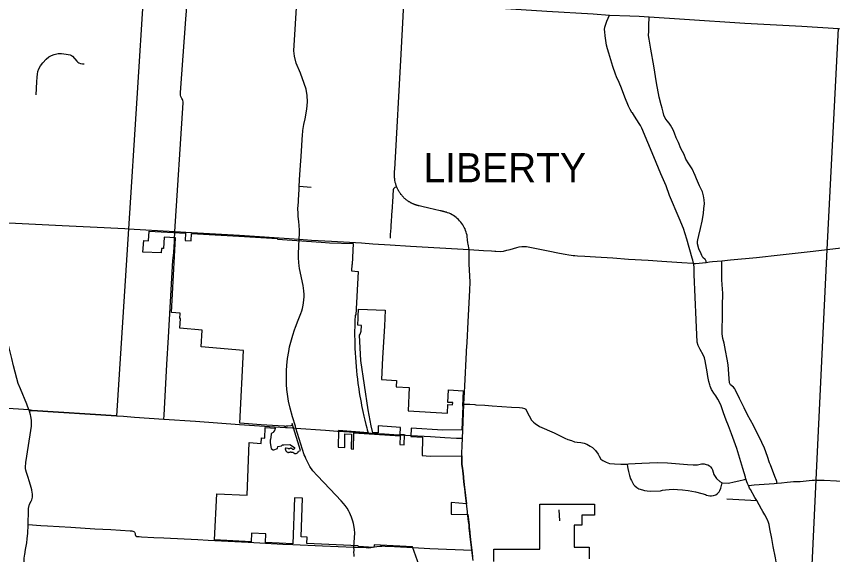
# Model space of a CAD drawing. Extents: x 1729596 to 1925846, y 659247 to 911751.
# Drawn here: x 1793175 to 1818365, y 790627 to 807237 of the extents above; entities that cross this region are included whole.
import ezdxf

# ---------------------------------------------------------------- set-up
doc = ezdxf.new("R2010")
doc.units = 0
for name, color, linetype in [('GM_X_City_Street', 7, 'Continuous'), ('GM_X_Corporation', 7, 'Continuous'), ('GM_X_County_Road', 7, 'Continuous'), ('GM_X_State_Route', 7, 'Continuous'), ('GM_X_Township', 7, 'Continuous'), ('GM_X_Township_Road', 7, 'Continuous'), ('GM_X_Township_Text', 7, 'Continuous')]:
    doc.layers.add(name, color=color, linetype=linetype)

msp = doc.modelspace()

# ---------------------------------------------------------------- linework, layer by layer
at = {"layer": 'GM_X_City_Street'}
for points in [[(1798056, 800391), (1798063, 800548)], [(1803593, 790860), (1803616, 791303), (1803610, 791407), (1803592, 791535), (1803581, 791586), (1803562, 791662), (1803522, 791785), (1803491, 791860), (1803460, 791928), (1803435, 791974), (1803382, 792063), (1803323, 792149), (1803275, 792210), (1803202, 792291), (1802860, 792647), (1802459, 793065), (1802327, 793219), (1802237, 793347), (1802189, 793427), (1802146, 793510), (1802106, 793595), (1802083, 793653), (1802061, 793711), (1801804, 794534), (1801785, 794592), (1801697, 794877), (1801622, 795149), (1801577, 795364), (1801553, 795508), (1801526, 795726), (1801515, 795873), (1801507, 796108), (1801512, 796313), (1801521, 796460), (1801544, 796679), (1801579, 796897), (1801608, 797041), (1801643, 797184), (1801704, 797397), (1801763, 797566), (1801790, 797645), (1801875, 797866), (1801954, 798071), (1801981, 798146), (1802004, 798222), (1802028, 798325), (1802041, 798401), (1802054, 798578), (1802056, 798612), (1802055, 798689), (1802052, 798741), (1802049, 798768), (1802040, 798846), (1802024, 798932), (1801916, 799454), (1801901, 799536), (1801889, 799641), (1801880, 799782), (1801880, 799852), (1801882, 799923), (1801901, 800359)], [(1801699, 794541), (1801804, 794534), (1802711, 794469), (1803088, 794442)], [(1805195, 794317), (1805349, 794307)], [(1809918, 792015), (1809918, 792014), (1809933, 791671)], [(1803969, 790844), (1804052, 790841), (1804223, 790866), (1804297, 790877), (1804388, 790887), (1804454, 790894), (1804503, 790896), (1804556, 790893)], [(1805411, 790847), (1805932, 790816), (1807231, 790763)]]:
    msp.add_lwpolyline(points, dxfattribs=at)
at = {"layer": 'GM_X_Corporation'}
for points in [[(1805912, 789433), (1805403, 790869), (1804215, 790928), (1804211, 790853), (1803721, 790877), (1803722, 790895), (1802140, 790967), (1802146, 791168), (1801964, 791178), (1802002, 792366), (1801754, 792380), (1801709, 790966), (1800866, 791005), (1800878, 791273), (1800432, 791295), (1800421, 791026), (1799291, 791085), (1799361, 792508), (1800301, 792459), (1800358, 794084), (1800732, 794059), (1800745, 794232), (1800840, 794226), (1800850, 794556), (1801177, 794531), (1801177, 794530), (1801171, 794528), (1801167, 794526), (1801164, 794523), (1801161, 794520), (1801159, 794516), (1801158, 794513), (1801157, 794509), (1801156, 794499), (1801152, 794484), (1801149, 794473), (1801144, 794460), (1801136, 794444), (1801131, 794435), (1801124, 794425), (1801117, 794416), (1801111, 794410), (1801105, 794403), (1801097, 794396), (1801057, 794378), (1801046, 794370), (1801040, 794358), (1801038, 794353), (1801037, 794349), (1801036, 794346), (1801035, 794342), (1801034, 794334), (1801015, 794183), (1801013, 794166), (1801010, 794148), (1801006, 794125), (1801005, 794119), (1801004, 794113), (1801004, 794107), (1801004, 794104), (1801004, 794102), (1801004, 794098), (1801004, 794092), (1801005, 794088), (1801006, 794083), (1801044, 793903), (1801076, 793875), (1801081, 793871), (1801084, 793869), (1801087, 793868), (1801092, 793865), (1801097, 793864), (1801100, 793863), (1801105, 793863), (1801111, 793862), (1801118, 793863), (1801122, 793864), (1801126, 793865), (1801230, 793905), (1801243, 793966), (1801357, 793982), (1801392, 794015), (1801434, 794020), (1801618, 794023), (1801754, 793933), (1801757, 793926), (1801759, 793919), (1801759, 793910), (1801757, 793900), (1801752, 793890), (1801748, 793886), (1801742, 793880), (1801732, 793875), (1801726, 793874), (1801720, 793873), (1801711, 793874), (1801703, 793877), (1801698, 793880), (1801693, 793884), (1801686, 793893), (1801676, 793902), (1801667, 793907), (1801657, 793909), (1801646, 793910), (1801638, 793909), (1801629, 793906), (1801619, 793902), (1801607, 793898), (1801595, 793897), (1801583, 793896), (1801571, 793897), (1801564, 793899), (1801556, 793901), (1801506, 793918), (1801497, 793919), (1801489, 793918), (1801482, 793914), (1801477, 793908), (1801474, 793903), (1801474, 793901), (1801473, 793897), (1801473, 793892), (1801475, 793878), (1801477, 793871), (1801479, 793864), (1801482, 793854), (1801487, 793844), (1801496, 793829), (1801505, 793818), (1801515, 793807), (1801525, 793798), (1801538, 793790), (1801540, 793788), (1801545, 793786), (1801549, 793784), (1801554, 793783), (1801561, 793782), (1801566, 793782), (1801570, 793782), (1801575, 793783), (1801582, 793785), (1801594, 793789), (1801606, 793792), (1801618, 793794), (1801629, 793795), (1801640, 793796), (1801650, 793796), (1801660, 793795), (1801677, 793793), (1801690, 793790), (1801706, 793785), (1801719, 793780), (1801741, 793765), (1801773, 793752), (1801811, 793754), (1801832, 793757), (1801855, 793773), (1801876, 793794), (1801883, 793816), (1801890, 793824), (1801945, 793843), (1801685, 794670), (1801687, 794665), (1801687, 794660), (1801688, 794655), (1801688, 794651), (1801687, 794646), (1801686, 794641), (1801682, 794632), (1801676, 794623), (1801669, 794616), (1801665, 794613), (1801657, 794609), (1801650, 794606), (1801644, 794605), (1801555, 794593), (1801526, 794589), (1801506, 794588), (1801484, 794587), (1801464, 794587), (1801447, 794588), (1801432, 794588), (1800727, 794638), (1800069, 794684), (1800187, 796930), (1798881, 797044), (1798908, 797551), (1798221, 797611), (1798237, 797910), (1798217, 797912), (1798226, 798077), (1797968, 798095), (1798088, 800399), (1797739, 800419), (1797716, 800075), (1797653, 800079), (1797641, 799936), (1797084, 799963), (1797107, 800322), (1797255, 800313), (1797272, 800613), (1798397, 800551), (1798384, 800322), (1798575, 800308), (1798585, 800540), (1800039, 800457), (1801236, 800382), (1801235, 800362), (1802581, 800268), (1802843, 800252), (1803573, 800232), (1803539, 799580), (1803531, 799580), (1803521, 799381), (1803720, 799367), (1803650, 798018), (1803630, 798018), (1803626, 797950), (1803625, 797907), (1803622, 797844), (1803621, 797776), (1803619, 797715), (1803615, 797472), (1803615, 797362), (1803616, 797275), (1803619, 797126), (1803624, 796988), (1803629, 796858), (1803638, 796706), (1803659, 796433), (1803671, 796297), (1803684, 796179), (1803700, 796040), (1803716, 795913), (1803741, 795740), (1803759, 795626), (1803776, 795519), (1803792, 795428), (1803803, 795369), (1803812, 795318), (1803830, 795229), (1803848, 795137), (1803866, 795049), (1803900, 794897), (1803929, 794774), (1803961, 794644), (1803989, 794539), (1804002, 794484), (1804028, 794390), (1803117, 794454), (1803108, 793948), (1803307, 793934), (1803315, 794360), (1803513, 794346), (1803505, 793891), (1803582, 793885), (1803590, 794385), (1805020, 794290), (1805010, 794022), (1805139, 794014), (1805152, 794324), (1805017, 794332), (1805027, 794547), (1804342, 794598), (1804342, 794383), (1804179, 794385), (1804129, 794602), (1804037, 795099), (1803808, 796623), (1803760, 797403), (1803781, 797434), (1803819, 797522), (1803830, 797703), (1803712, 797708), (1803713, 797757), (1803719, 797888), (1803723, 797985), (1803733, 798207), (1804556, 798175), (1804535, 797675), (1804476, 796703), (1804448, 796035), (1804906, 795999), (1804898, 795810), (1805300, 795785), (1805269, 795066), (1806477, 794993), (1806488, 795256), (1806639, 795253), (1806642, 795323), (1806493, 795326), (1806509, 795712), (1806963, 795684), (1806943, 795206), (1806953, 795205), (1806921, 794476), (1806338, 794471), (1805355, 794530), (1805348, 794275), (1805706, 794254), (1805701, 793689), (1805942, 793669), (1806920, 793676), (1806923, 793473), (1806927, 793423), (1806942, 793287), (1806949, 793228), (1806961, 793116), (1806970, 793038), (1806976, 792990), (1806999, 792792), (1807038, 792455), (1807068, 792201), (1806589, 792240), (1806589, 791873), (1807104, 791869), (1807144, 791544), (1807151, 791476), (1807153, 791456), (1807155, 791437), (1807184, 791193), (1807215, 790917), (1807231, 790763), (1807256, 790572)], [(1807905, 790417), (1807905, 790798), (1809332, 790798), (1809332, 792187), (1811020, 792187), (1811020, 791842), (1810623, 791842), (1810623, 791542), (1810391, 791542), (1810391, 790858), (1810855, 790858), (1810855, 790494)]]:
    msp.add_lwpolyline(points, dxfattribs=at)
at = {"layer": 'GM_X_County_Road'}
for points in [[(1797153, 808138), (1797813, 808094), (1798478, 808064), (1798746, 808039), (1801838, 807850), (1803855, 807737), (1803954, 807731), (1804251, 807713), (1804397, 807702), (1804736, 807682), (1805136, 807661), (1806811, 807563), (1808119, 807486), (1809547, 807399), (1810973, 807310), (1811477, 807276), (1812106, 807251), (1812390, 807244), (1812704, 807223), (1813792, 807154), (1815652, 807028), (1817412, 806933), (1818544, 806864), (1818913, 806840)], [(1798065, 800600), (1798320, 804569), (1798319, 804604), (1798313, 804638), (1798300, 804669), (1798280, 804702), (1798255, 804766), (1798245, 804805), (1798244, 804890), (1798409, 807145), (1798478, 808064)], [(1802014, 803669), (1802020, 803715), (1802050, 803896), (1802085, 804077), (1802143, 804374), (1802164, 804595), (1802153, 804796), (1802119, 804993), (1802057, 805167), (1801945, 805481), (1801815, 805789), (1801757, 806010), (1801735, 806174), (1801838, 807850)], [(1804844, 802293), (1804843, 802302), (1804842, 802313), (1804841, 802319), (1804844, 802370), (1804849, 802458), (1804852, 802514), (1805055, 806072), (1805110, 807232), (1805136, 807661)], [(1801953, 802776), (1801962, 802915), (1802006, 803596), (1802014, 803669)], [(1801927, 802355), (1801953, 802776)], [(1801904, 801987), (1801904, 801993), (1801927, 802355)], [(1806860, 800922), (1806855, 800928), (1806820, 800964), (1806783, 800999), (1806745, 801031), (1806705, 801061), (1806663, 801090), (1806620, 801115), (1806575, 801139), (1806529, 801160), (1806483, 801179), (1806464, 801186), (1806456, 801189), (1806449, 801191), (1806443, 801192), (1806431, 801196), (1806423, 801198), (1806414, 801200), (1806401, 801204), (1806388, 801207), (1806381, 801209), (1806371, 801212), (1806359, 801215), (1806347, 801218), (1806336, 801220), (1806324, 801223), (1806314, 801226), (1806302, 801229), (1806289, 801233), (1806283, 801235), (1806276, 801237), (1806266, 801239), (1806257, 801241), (1805899, 801322), (1805693, 801369), (1805607, 801388), (1805581, 801394), (1805570, 801397), (1805562, 801399), (1805554, 801401), (1805547, 801403), (1805539, 801405), (1805530, 801408), (1805521, 801412), (1805511, 801415), (1805503, 801418), (1805495, 801421), (1805486, 801424), (1805470, 801430), (1805454, 801436), (1805439, 801442), (1805424, 801449), (1805408, 801455), (1805393, 801462), (1805386, 801466), (1805378, 801470), (1805363, 801477), (1805349, 801485), (1805334, 801493), (1805319, 801501), (1805305, 801510), (1805291, 801518), (1805277, 801527), (1805263, 801537), (1805249, 801546), (1805236, 801556), (1805223, 801566), (1805209, 801576), (1805196, 801586), (1805184, 801597), (1805171, 801608), (1805158, 801619), (1805146, 801630), (1805134, 801642), (1805122, 801654), (1805111, 801666), (1805099, 801678), (1805088, 801690), (1805077, 801703), (1805066, 801715), (1805056, 801728), (1805045, 801741), (1805035, 801755), (1805025, 801768), (1805016, 801782), (1805006, 801795), (1804997, 801809), (1804988, 801823), (1804980, 801838), (1804971, 801852), (1804963, 801867), (1804955, 801881), (1804948, 801896), (1804940, 801911), (1804933, 801926), (1804926, 801941), (1804920, 801957), (1804914, 801972), (1804911, 801979), (1804907, 801988), (1804896, 802019), (1804882, 802065), (1804869, 802115), (1804855, 802189), (1804854, 802197), (1804852, 802214), (1804850, 802230), (1804849, 802247), (1804848, 802263), (1804847, 802274), (1804844, 802293), (1804844, 802293)], [(1801882, 801567), (1801899, 801907), (1801904, 801987)], [(1801907, 800780), (1801897, 800907), (1801875, 801062), (1801868, 801169), (1801863, 801294), (1801880, 801518), (1801882, 801567)], [(1790816, 800981), (1790957, 800973), (1791328, 800949), (1791805, 800926), (1792317, 800900), (1794586, 800781), (1795455, 800738), (1796520, 800687)], [(1807152, 800038), (1807113, 800206), (1807110, 800245), (1807102, 800345), (1807090, 800444), (1807086, 800469), (1807083, 800485), (1807071, 800534), (1807057, 800582), (1807040, 800629), (1807020, 800676), (1806999, 800721), (1806974, 800766), (1806948, 800808), (1806919, 800850), (1806888, 800890), (1806860, 800922)], [(1796520, 800687), (1796632, 800682), (1798065, 800600), (1798576, 800566), (1800057, 800481), (1801901, 800359), (1802286, 800331), (1802901, 800301), (1803824, 800245), (1804171, 800217), (1804715, 800188)], [(1801901, 800359), (1801911, 800535), (1801912, 800648), (1801908, 800771), (1801907, 800780)], [(1804715, 800188), (1804715, 800188), (1805337, 800150)], [(1805337, 800150), (1807152, 800038)], [(1807071, 796914), (1807086, 797176), (1807115, 797807), (1807169, 798793), (1807176, 799039), (1807148, 799599), (1807152, 800038)], [(1807152, 800038), (1807595, 800015), (1807835, 800002), (1807942, 799990), (1807972, 799989)], [(1807972, 799989), (1808102, 799984), (1808211, 799987), (1808312, 800022), (1808409, 800047), (1808615, 800108), (1808695, 800123), (1808776, 800134), (1808826, 800138), (1808921, 800131), (1808973, 800123), (1809585, 800007), (1809940, 799932), (1810107, 799900), (1810229, 799878), (1810291, 799868), (1810353, 799860), (1810412, 799854), (1810492, 799848), (1810714, 799837), (1811046, 799817), (1811584, 799784), (1812065, 799747), (1812676, 799710), (1813093, 799684), (1813708, 799647), (1814050, 799626), (1814069, 799619)], [(1814566, 799659), (1814662, 799670), (1814940, 799695), (1815216, 799728), (1816018, 799800), (1816744, 799881), (1817764, 799993), (1818194, 800042), (1818804, 800110)], [(1814069, 799619), (1814069, 799619), (1814083, 799612), (1814092, 799610), (1814102, 799610), (1814111, 799611), (1814133, 799614), (1814460, 799647), (1814566, 799659)], [(1806919, 793655), (1806922, 793759), (1806932, 793983), (1806942, 794217), (1806953, 794458), (1806989, 795273), (1807017, 795829), (1807070, 796879), (1807071, 796914)], [(1807056, 792297), (1807038, 792455), (1807014, 792660), (1806999, 792792), (1806976, 792990), (1806970, 793038), (1806961, 793116), (1806949, 793228), (1806942, 793287), (1806927, 793423), (1806923, 793473), (1806920, 793526), (1806920, 793540), (1806918, 793583), (1806919, 793655)], [(1807100, 791929), (1807098, 791944), (1807056, 792297)], [(1807231, 790763), (1807184, 791193), (1807153, 791456), (1807144, 791544), (1807129, 791648), (1807100, 791929)], [(1803602, 790572), (1803596, 790635), (1803594, 790699), (1803595, 790763), (1803593, 790860)], [(1807271, 790450), (1807231, 790763)]]:
    msp.add_lwpolyline(points, dxfattribs=at)
at = {"layer": 'GM_X_State_Route'}
for points in [[(1814046, 799719), (1814033, 799773), (1813866, 800366), (1813763, 800686), (1813633, 801011), (1813335, 801709), (1813229, 802008), (1813066, 802380), (1812846, 802906), (1812474, 803784), (1812432, 803871), (1812398, 803934), (1812252, 804156), (1812185, 804255), (1812173, 804274), (1812117, 804367), (1812069, 804464), (1811955, 804745), (1811845, 805016), (1811772, 805192), (1811699, 805366), (1811663, 805457), (1811586, 805686), (1811462, 806103), (1811422, 806230), (1811390, 806346), (1811366, 806494), (1811344, 806636), (1811331, 806756), (1811328, 806834), (1811339, 806907), (1811363, 807000), (1811396, 807084), (1811477, 807276)], [(1815789, 792708), (1815764, 792762), (1815738, 792824), (1815720, 792872), (1815688, 792969), (1815675, 793019), (1815594, 793291), (1815404, 793901), (1815288, 794246), (1815247, 794360), (1815149, 794599), (1815080, 794780), (1815000, 794999), (1814921, 795216), (1814870, 795332), (1814823, 795426), (1814760, 795528), (1814701, 795610), (1814642, 795695), (1814627, 795722), (1814603, 795775), (1814586, 795824), (1814574, 795867), (1814549, 795975), (1814518, 796129), (1814494, 796266), (1814433, 796604), (1814409, 796703), (1814373, 796794), (1814274, 796960), (1814214, 797077), (1814186, 797179), (1814154, 797878), (1814090, 799272), (1814087, 799504), (1814069, 799619), (1814046, 799719)], [(1793626, 794462), (1793626, 794462), (1793641, 794594), (1793644, 794648), (1793641, 794771), (1793623, 794897), (1793613, 794945), (1793580, 795059), (1793566, 795094), (1793498, 795270), (1793303, 795745), (1793237, 795913), (1793188, 796062), (1793091, 796453), (1793034, 796681), (1792957, 797013), (1792916, 797174), (1792881, 797288), (1792802, 797495), (1792672, 797742), (1792629, 797811), (1792556, 797903), (1792444, 798033), (1792099, 798333)], [(1793540, 791608), (1793549, 791942), (1793553, 792041), (1793562, 792113), (1793568, 792137), (1793585, 792183), (1793636, 792281), (1793653, 792321), (1793664, 792356), (1793672, 792401), (1793674, 792449), (1793673, 792501), (1793669, 792548), (1793654, 792626), (1793633, 792702), (1793579, 792877), (1793527, 793036), (1793489, 793158), (1793469, 793235), (1793462, 793288), (1793461, 793331), (1793468, 793471), (1793556, 793991), (1793626, 794462)], [(1816266, 788827), (1816308, 788989), (1816463, 789546), (1816611, 790147), (1816623, 790230), (1816624, 790350), (1816620, 790409), (1816599, 790530), (1816533, 790876), (1816487, 791123), (1816430, 791427), (1816402, 791554), (1816384, 791615), (1816350, 791700), (1816268, 791852), (1816208, 791960), (1816169, 792032), (1816020, 792294), (1815964, 792391), (1815825, 792638), (1815801, 792684), (1815789, 792708)], [(1793482, 788892), (1793480, 788936), (1793465, 789394), (1793462, 789511), (1793439, 789955), (1793430, 790164), (1793422, 790343), (1793421, 790408), (1793422, 790509), (1793431, 790592), (1793438, 790637), (1793462, 790782), (1793496, 790992), (1793514, 791113), (1793528, 791294), (1793538, 791541), (1793538, 791555), (1793540, 791608)]]:
    msp.add_lwpolyline(points, dxfattribs=at)
at = {"layer": 'GM_X_Township'}
for points in [[(1797107, 808141), (1796898, 804715), (1796632, 800682), (1796269, 794910), (1793660, 795080), (1793566, 795094), (1792419, 795165)], [(1817250, 778977), (1817281, 779754), (1817338, 781221), (1817524, 785929), (1817856, 792932), (1818194, 800042), (1818544, 806864)]]:
    msp.add_lwpolyline(points, dxfattribs=at)
at = {"layer": 'GM_X_Township_Road'}
for points in [[(1814460, 799647), (1814457, 799683), (1814438, 799723), (1814426, 799738), (1814361, 799801), (1814324, 799859), (1814308, 799911), (1814238, 800059), (1814198, 800221), (1814195, 800291), (1814204, 800342), (1814236, 800470), (1814285, 800688), (1814336, 800919), (1814377, 801149), (1814391, 801304), (1814408, 801451), (1814405, 801572), (1814380, 801701), (1814344, 801826), (1814258, 802009), (1814163, 802221), (1814122, 802323), (1814025, 802532), (1813931, 802687), (1813839, 802828), (1813782, 802973), (1813683, 803164), (1813603, 803348), (1813540, 803487), (1813483, 803630), (1813441, 803731), (1813365, 803878), (1813321, 803941), (1813260, 804011), (1813199, 804097), (1813157, 804183), (1813132, 804277), (1813104, 804407), (1813078, 804508), (1813014, 804741), (1812925, 805181), (1812850, 805707), (1812757, 806222), (1812701, 806533), (1812684, 806644), (1812689, 806784), (1812689, 806949), (1812704, 807223)], [(1793788, 804820), (1793812, 805216), (1793820, 805355), (1793827, 805457), (1793843, 805540), (1793869, 805616), (1793918, 805709), (1793990, 805801), (1794094, 805915), (1794181, 805983), (1794259, 806027), (1794348, 806060), (1794464, 806087), (1794571, 806092), (1794710, 806073), (1794716, 806071), (1794836, 806048), (1794873, 806032), (1794905, 806009), (1795045, 805852), (1795072, 805827), (1795107, 805803), (1795159, 805782), (1795219, 805773), (1795271, 805772)], [(1801904, 801993), (1802275, 801968)], [(1804717, 800389), (1804722, 800491), (1804731, 800619), (1804738, 800701), (1804739, 800737), (1804744, 800820), (1804748, 800873), (1804755, 800974), (1804758, 801023), (1804763, 801096), (1804773, 801250), (1804779, 801319), (1804785, 801417), (1804788, 801465), (1804791, 801506), (1804795, 801576), (1804799, 801628), (1804802, 801696), (1804807, 801756), (1804807, 801763), (1804811, 801828), (1804814, 801876), (1804815, 801891), (1804816, 801899), (1804817, 801905), (1804819, 801910), (1804826, 801925), (1804835, 801938), (1804846, 801949), (1804859, 801958), (1804868, 801963), (1804911, 801979)], [(1798063, 800548), (1798065, 800600)], [(1797725, 794811), (1797735, 794932), (1797817, 796492), (1797873, 797335), (1798009, 799702), (1798031, 799951), (1798052, 800293), (1798056, 800391)], [(1816651, 792830), (1816647, 792855), (1816641, 792880), (1816629, 792919), (1816581, 793042), (1816451, 793399), (1816421, 793459), (1816355, 793658), (1816258, 793913), (1816181, 794093), (1815926, 794609), (1815735, 794947), (1815631, 795158), (1815491, 795447), (1815369, 795699), (1815345, 795744), (1815306, 795795), (1815215, 795872), (1815206, 795883), (1815192, 795907), (1815184, 795934), (1815174, 796067), (1815140, 796486), (1815112, 796657), (1815062, 796925), (1815015, 797154), (1814977, 797297), (1814956, 797438), (1814956, 797628), (1814964, 797910), (1814967, 798125), (1814970, 798293), (1814972, 798691), (1814969, 798822), (1814950, 799110), (1814945, 799491), (1814940, 799695)], [(1806989, 795273), (1807117, 795270), (1807173, 795267), (1807328, 795256), (1807350, 795255)], [(1807350, 795255), (1807635, 795237), (1807855, 795223), (1808153, 795203), (1808452, 795178), (1808700, 795170), (1808780, 795159), (1808857, 795134), (1808893, 795112), (1808921, 795070), (1808995, 794914), (1809077, 794780), (1809134, 794713), (1809181, 794675), (1809315, 794586), (1809775, 794384), (1810102, 794223), (1810194, 794185), (1810306, 794145), (1810398, 794113), (1810483, 794098), (1810591, 794085), (1810692, 794070), (1810784, 794039), (1810884, 793980), (1810951, 793937), (1811044, 793841), (1811125, 793727), (1811163, 793664), (1811214, 793578), (1811269, 793532), (1811376, 793484), (1811483, 793443), (1811637, 793425), (1811828, 793419), (1812029, 793424), (1812070, 793431), (1812481, 793453), (1812954, 793470), (1813265, 793463), (1813884, 793410), (1814063, 793397), (1814191, 793404), (1814314, 793426), (1814359, 793429), (1814395, 793428), (1814459, 793413), (1814511, 793395), (1814563, 793364), (1814591, 793334), (1814633, 793291), (1814655, 793246), (1814700, 793097), (1814777, 792975), (1814880, 792886), (1814956, 792840), (1815149, 792831), (1815322, 792872), (1815465, 792907), (1815640, 792951), (1815688, 792969)], [(1793580, 795059), (1793615, 795073), (1793660, 795080), (1796269, 794910), (1796478, 794896)], [(1796478, 794896), (1796818, 794874), (1797725, 794811), (1798705, 794743), (1800065, 794648), (1801142, 794575), (1801482, 794551), (1801528, 794554), (1801699, 794541)], [(1803088, 794442), (1803098, 794441), (1803639, 794404), (1803811, 794394), (1804136, 794373), (1804538, 794352), (1804829, 794335), (1805188, 794317), (1805195, 794317)], [(1805349, 794307), (1805354, 794307), (1805955, 794273), (1806396, 794247), (1806759, 794225), (1806942, 794217)], [(1812029, 793424), (1812036, 793334), (1812042, 793281), (1812062, 793196), (1812094, 793072), (1812129, 792968), (1812154, 792914), (1812187, 792850), (1812224, 792792), (1812261, 792747), (1812318, 792700), (1812382, 792663), (1812428, 792644), (1812523, 792618), (1812562, 792610), (1812642, 792596), (1812736, 792584), (1813056, 792597), (1813119, 792618), (1813202, 792629), (1813316, 792639), (1813448, 792647), (1813574, 792641), (1813729, 792631), (1813908, 792606), (1814128, 792562), (1814332, 792515), (1814438, 792479), (1814476, 792467), (1814570, 792444), (1814631, 792447), (1814692, 792457), (1814755, 792475), (1814811, 792519), (1814861, 792569), (1814883, 792608), (1814913, 792682), (1814956, 792840)], [(1815764, 792762), (1815780, 792766), (1815942, 792781), (1816558, 792823), (1816651, 792830), (1816788, 792844), (1816963, 792864), (1817060, 792876), (1817156, 792882), (1817289, 792880), (1817364, 792883), (1817732, 792925), (1817802, 792929), (1817856, 792932), (1817866, 792931), (1817878, 792931)], [(1817878, 792931), (1817995, 792928), (1818106, 792923), (1818482, 792901), (1818787, 792885), (1819262, 792857), (1819834, 792826), (1820206, 792804), (1820486, 792789), (1820816, 792770), (1821218, 792749), (1821979, 792708), (1822434, 792685), (1822684, 792674)], [(1815103, 792350), (1816020, 792294)], [(1793538, 791555), (1793933, 791531), (1794136, 791516), (1794855, 791471), (1795594, 791427), (1796096, 791400), (1796690, 791365), (1796735, 791362), (1796775, 791352), (1796803, 791340), (1796825, 791317), (1796840, 791284), (1796846, 791248), (1796852, 791221), (1796866, 791206), (1796894, 791190), (1796926, 791184), (1796968, 791184), (1797033, 791181), (1797419, 791162), (1797725, 791151), (1798779, 791092), (1799098, 791075), (1800325, 791009), (1801401, 790953), (1801709, 790937), (1802620, 790902), (1803593, 790860)], [(1803593, 790860), (1803677, 790856), (1803969, 790844)], [(1804556, 790893), (1804842, 790876), (1805411, 790847)]]:
    msp.add_lwpolyline(points, dxfattribs=at)

# ---------------------------------------------------------------- texts
at = {"layer": 'GM_X_Township_Text'}
msp.add_text('LIBERTY', height=900, rotation=0, dxfattribs=at).set_placement((1805738, 802117))

doc.saveas('drawing.dxf')
